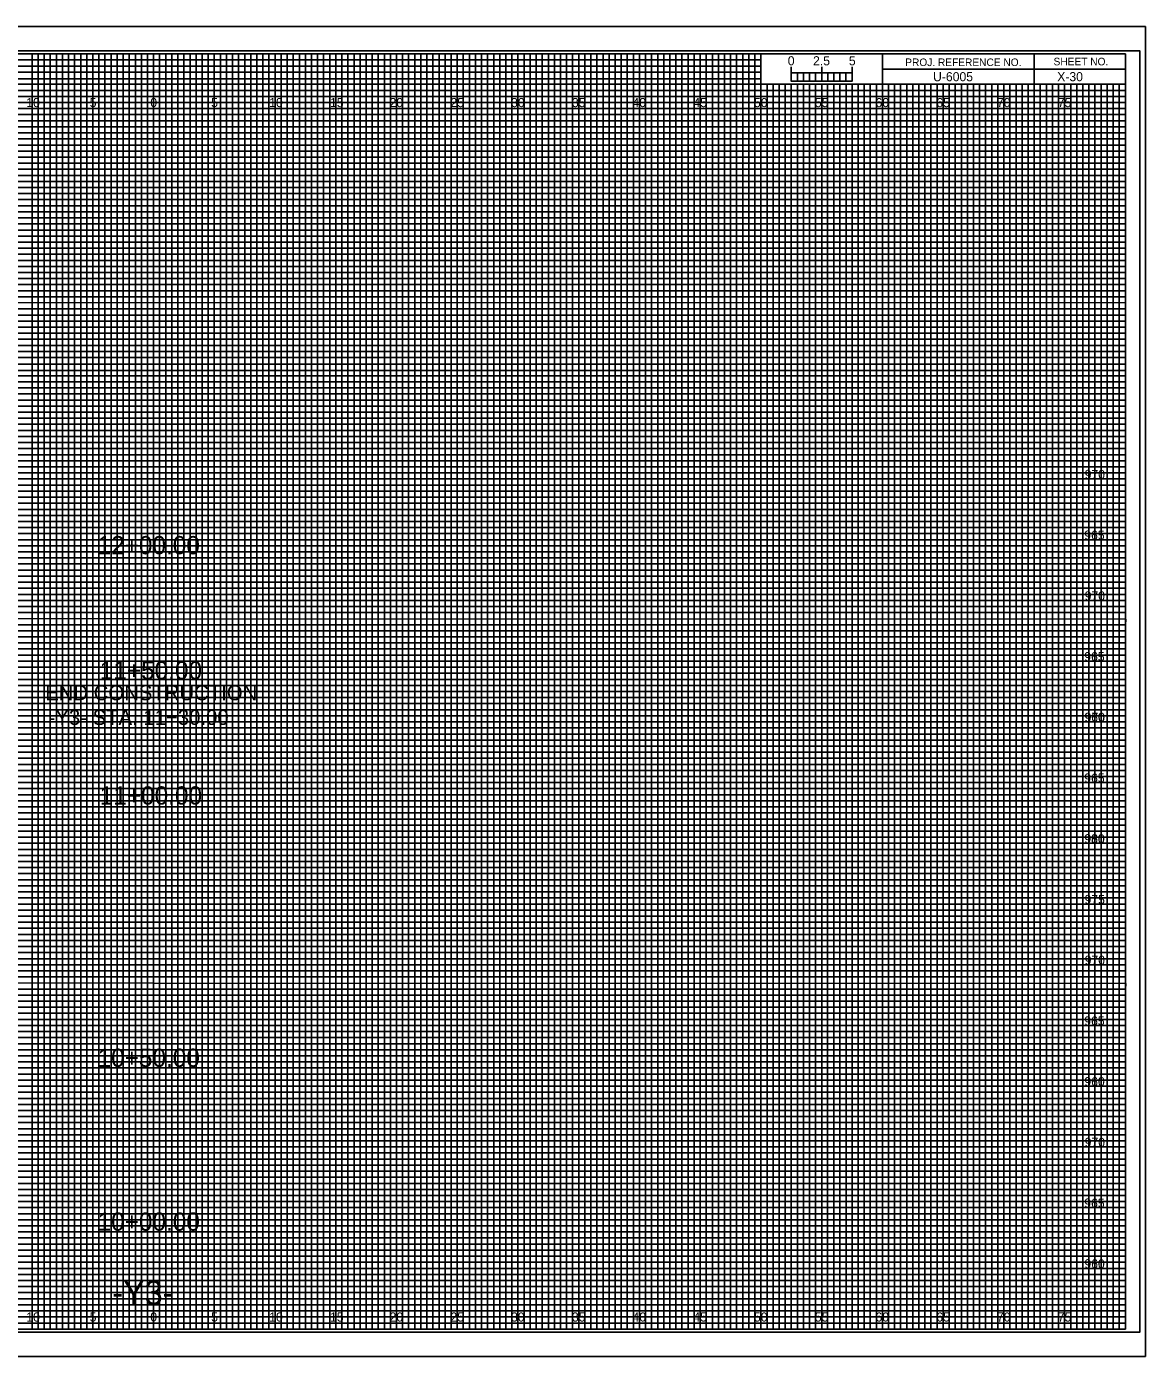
# Model space of a CAD drawing. Extents: x -7 to 162, y -2 to 107.
# Drawn here: x 69.5 to 161.7, y -2.3 to 107.3 of the extents above; entities that cross this region are included whole.
import ezdxf

# ---------------------------------------------------------------- set-up
doc = ezdxf.new("R2010")
doc.units = 0
for name, color, linetype in [('Prop XS Alignment Label', 7, 'Continuous'), ('Prop XS Bar Scale Labels', 7, 'Continuous'), ('Prop XS Elevation Labels', 7, 'Continuous'), ('Prop XS Label Text', 7, 'Continuous'), ('Prop XS Offset Labels', 7, 'Continuous'), ('Prop XS Project Number', 7, 'Continuous'), ('Prop XS Sheet Number', 7, 'Continuous'), ('Prop XS Station Labels', 7, 'Continuous'), ('Sheet Cross Section CELL', 7, 'Continuous'), ('Sheet Cross Section Grid Major CELL', 7, 'Continuous'), ('Sheet Cross Section Grid Middle CELL', 7, 'Continuous'), ('Sheet Cross Section Grid Minor 1 CELL', 7, 'Continuous'), ('Sheet Cross Section Grid Minor 2 CELL', 7, 'Continuous'), ('Sheet Cross Section Scale CELL', 7, 'Continuous'), ('Sheet Cutting Line CELL', 7, 'Continuous'), ('Sheet DOT Grid CELL', 7, 'Continuous'), ('Sheet Plot Border Inside CELL', 7, 'Continuous'), ('Sheet Plot Border Outside CELL', 7, 'Continuous')]:
    doc.layers.add(name, color=color, linetype=linetype)

msp = doc.modelspace()

# ---------------------------------------------------------------- linework, layer by layer
at = {"layer": 'Sheet Cross Section CELL'}
for p, q in [((152.5, 105), (152.5, 102.5)), ((152.5, 102.5), (152.5, 105)), ((160, 103.75), (140, 103.75)), ((140, 103.75), (140, 102.5)), ((140, 102.5), (160, 102.5))]:
    msp.add_line(p, q, dxfattribs=at)
for points in [[(160, 105), (0, 105), (0, 0), (160, 0)], [(140, 105), (130, 105), (130, 102.52), (140, 102.52)], [(160, 105), (140, 105), (140, 102.5), (160, 102.5)]]:
    msp.add_lwpolyline(points, close=True, dxfattribs=at)
at = {"layer": 'Sheet Cross Section Grid Major CELL'}
for p, q in [((75, 105), (70, 105)), ((70, 105), (70, 0)), ((75, 0), (75, 105)), ((85, 105), (80, 105)), ((80, 105), (80, 0)), ((85, 0), (85, 105)), ((95, 105), (90, 105)), ((90, 105), (90, 0)), ((95, 0), (95, 105)), ((105, 105), (100, 105)), ((100, 105), (100, 0)), ((105, 0), (105, 105)), ((115, 105), (110, 105)), ((110, 105), (110, 0)), ((115, 0), (115, 105)), ((125, 105), (120, 105)), ((120, 105), (120, 0)), ((125, 0), (125, 105)), ((130, 105), (130, 0)), ((135, 0), (135, 102.5)), ((145, 102.5), (140, 102.5)), ((140, 102.5), (140, 0)), ((145, 0), (145, 102.5)), ((155, 102.5), (150, 102.5)), ((150, 102.5), (150, 0)), ((155, 0), (155, 102.5)), ((70, 0), (65, 0)), ((80, 0), (75, 0)), ((90, 0), (85, 0)), ((100, 0), (95, 0)), ((110, 0), (105, 0)), ((120, 0), (115, 0)), ((130, 0), (125, 0)), ((140, 0), (135, 0)), ((150, 0), (145, 0)), ((160, 0), (155, 0)), ((160, 0), (160, 0))]:
    msp.add_line(p, q, dxfattribs=at)
for points in [[(0, 100), (160, 100), (160, 95), (0, 95)], [(0, 90), (160, 90), (160, 85), (0, 85)], [(0, 80), (160, 80), (160, 75), (0, 75)], [(0, 70), (160, 70), (160, 65), (0, 65)], [(0, 60), (160, 60), (160, 55), (0, 55)], [(0, 50), (160, 50), (160, 45), (0, 45)], [(0, 40), (160, 40), (160, 35), (0, 35)], [(0, 30), (160, 30), (160, 25), (0, 25)], [(0, 20), (160, 20), (160, 15), (0, 15)], [(0, 10), (160, 10), (160, 5), (0, 5)]]:
    msp.add_lwpolyline(points, dxfattribs=at)
at = {"layer": 'Sheet Cross Section Grid Middle CELL'}
for points in [[(67.5, 105), (72.5, 105), (72.5, 0), (77.5, 0), (77.5, 105), (82.5, 105), (82.5, 0), (87.5, 0), (87.5, 105), (92.5, 105), (92.5, 0), (97.5, 0), (97.5, 105), (102.5, 105), (102.5, 0), (107.5, 0), (107.5, 105), (112.5, 105), (112.5, 0), (117.5, 0), (117.5, 105), (122.5, 105), (122.5, 0), (127.5, 0), (127.5, 105), (129.97, 105), (130, 105), (130, 102.5), (132.5, 102.5), (132.5, 0), (137.5, 0), (137.5, 102.5), (142.5, 102.5), (142.5, 0), (147.5, 0), (147.5, 102.5), (152.5, 102.5), (152.5, 0), (157.5, 0), (157.5, 102.5)], [(0, 102.5), (137.5, 102.5)], [(0, 92.5), (160, 92.5), (160, 97.5), (0, 97.5)], [(0, 82.5), (160, 82.5), (160, 87.5), (0, 87.5)], [(0, 72.5), (160, 72.5), (160, 77.5), (0, 77.5)], [(0, 62.5), (160, 62.5), (160, 67.5), (0, 67.5)], [(0, 52.5), (160, 52.5), (160, 57.5), (0, 57.5)], [(0, 42.5), (160, 42.5), (160, 47.5), (0, 47.5)], [(0, 32.5), (160, 32.5), (160, 37.5), (0, 37.5)], [(0, 22.5), (160, 22.5), (160, 27.5), (0, 27.5)], [(0, 12.5), (160, 12.5), (160, 17.5), (0, 17.5)], [(0, 2.5), (160, 2.5), (160, 7.5), (0, 7.5)]]:
    msp.add_lwpolyline(points, dxfattribs=at)
at = {"layer": 'Sheet Cross Section Grid Minor 1 CELL'}
for p, q in [((0, 104.5), (130, 104.5)), ((130, 104.5), (130, 103.99)), ((130, 103.99), (0, 103.99)), ((0, 103.5), (130, 103.5)), ((130, 102.95), (0, 102.95)), ((130, 103.5), (130, 102.95)), ((0, 102), (160, 102))]:
    msp.add_line(p, q, dxfattribs=at)
for points in [[(0, 101.5), (135, 101.5), (160, 101.5), (160, 101), (0, 101)], [(0, 100.5), (160, 100.5), (160, 99.5), (0, 99.5)], [(0, 99), (160, 99), (160, 98.5), (0, 98.49)], [(0, 98), (160, 98), (160, 97), (0, 97)], [(0, 96.5), (160, 96.5), (160, 96), (0, 96)], [(0, 95.5), (160, 95.5), (160, 94.5), (0, 94.5)], [(0, 94), (160, 94), (160, 93.5), (0, 93.5)], [(0, 93), (160, 93), (160, 92), (0, 92)], [(0, 91.5), (160, 91.5), (160, 91), (0, 91)], [(0, 90.5), (160, 90.5), (160, 89.5), (0, 89.5)], [(0, 89), (160, 89), (160, 88.5), (0, 88.5)], [(0, 88), (160, 88), (160, 86.98), (160, 86.5), (160, 86), (0, 86)], [(0, 87), (160, 87), (160, 86.5), (0, 86.5)], [(0, 85.5), (160, 85.5), (160, 84.5), (0, 84.52)], [(0, 84.52), (160, 84.5), (160, 84), (0, 84)], [(0, 83.5), (160, 83.5), (160, 83), (0, 83)], [(0, 82), (160, 82), (160, 81.5), (0, 81.5)], [(0, 81), (160, 81), (160, 80.5), (0, 80.5)], [(-0.04, 79.45), (160, 79.45), (160, 78.94), (-0.04, 78.94)], [(0, 78.5), (160, 78.5), (160, 78), (0, 78)], [(0, 77), (160, 77), (160, 76.5), (0, 76.5)], [(0, 76), (160, 76), (160, 75.5), (0, 75.5)], [(0, 74.5), (160, 74.5), (160, 74), (0, 74)], [(0, 73.5), (160, 73.5), (160, 73), (0, 73)], [(0, 72), (160, 72), (160, 71.5), (0, 71.5)], [(0, 71), (160, 71), (160, 70.5), (0, 70.5)], [(0, 69.5), (160, 69.5), (160, 68.99), (0, 69)], [(0, 68.5), (160, 68.5), (160, 68), (0, 68)], [(0, 67), (160, 67), (160, 66.5), (0, 66.5)], [(0, 66), (160, 66), (160, 65.5), (0, 65.5)], [(0, 64.5), (160, 64.5), (160, 64), (0, 64)], [(0, 63.5), (160, 63.5), (160, 63), (0, 63)], [(0, 62), (160, 62), (160, 61.5), (0, 61.5)], [(0, 61), (160, 61), (160, 60.5), (0, 60.5)], [(0, 59.5), (160, 59.5), (160, 59), (0, 59)], [(0, 58.5), (160.03, 58.45), (160, 58), (0, 58)], [(0, 57), (160, 57), (160, 56.5), (0, 56.5)], [(0, 56), (160, 56), (160, 55.5), (0, 55.5)], [(0, 54.5), (160, 54.5), (160, 54), (0, 54)], [(0, 53.5), (160, 53.5), (160, 53), (0, 53)], [(0, 52), (160, 52), (160, 51.5), (0, 51.5)], [(0, 51), (160, 51), (160, 50.5), (0, 50.5)], [(0, 49.5), (160, 49.5), (160, 49), (0, 49)], [(0, 48.5), (160, 48.5), (160, 48), (0, 48)], [(0, 47), (160, 47), (160, 46.5), (0, 46.5)], [(0, 46), (160, 46), (160, 45.5), (0, 45.5)], [(0, 44.5), (160, 44.5), (160, 44), (0, 44)], [(0, 43.5), (160, 43.5), (160, 43), (0, 43)], [(0, 42), (160, 42), (160, 41.5), (0, 41.5)], [(0, 41), (160, 41), (160, 40.5), (0, 40.5)], [(0, 39.5), (160, 39.5), (160, 38.99), (0, 39)], [(0, 38.5), (160, 38.5), (160, 38), (0, 38)], [(0, 37), (160, 37), (160, 36.5), (0, 36.5)], [(0, 36), (160, 36), (160, 35.5), (0, 35.5)], [(0, 34.5), (160, 34.5), (160, 34), (0, 34)], [(0, 33.5), (160, 33.5), (160, 33), (0, 33)], [(0, 32), (160, 32), (160, 31.5), (0, 31.5)], [(0, 31), (160, 31), (160, 30.5), (0, 30.5)], [(0, 29.5), (160, 29.5), (160, 29), (0, 29)], [(0, 28.5), (160.03, 28.46), (160, 28), (0, 28)], [(0, 27), (160, 27), (160, 26.5), (0, 26.5)], [(0, 26), (160, 26), (160, 25.5), (0, 25.5)], [(0, 24.5), (160, 24.5), (160, 24), (0, 24)], [(0, 23.5), (160, 23.5), (160, 23), (0, 23)], [(0, 22), (160, 22), (160, 21.5), (0, 21.5)], [(0, 21), (160, 21), (160, 20.5), (0, 20.5)], [(0, 19.5), (160, 19.5), (160, 19), (0, 19)], [(0, 18.5), (160, 18.5), (160, 18), (0, 18)], [(0, 17), (160, 17), (160, 16.5), (0, 16.5)], [(0, 16), (160, 16), (160, 15.5), (0, 15.5)], [(0, 14.5), (160, 14.5), (160, 14), (0, 14)], [(0, 13.5), (160, 13.5), (160, 13), (0, 13)], [(0, 12), (160, 12), (160, 11.5), (0, 11.5)], [(0, 11), (160, 11), (160, 10.5), (0, 10.5)], [(0, 9.5), (160, 9.5), (160, 9), (0, 9)], [(0, 8.5), (160, 8.5), (160, 8), (0, 8)], [(0, 7), (160, 7), (160, 6.5), (0, 6.5)], [(0, 6), (160, 6), (160, 5.5), (0, 5.5)], [(0, 4.5), (160, 4.5), (160, 4), (0, 4)], [(0, 3.5), (160, 3.5), (160, 3), (0, 3)], [(0, 2), (160, 2), (160, 1.5), (0, 1.5)], [(0, 1), (160, 1), (160, 0.5), (0, 0.5)]]:
    msp.add_lwpolyline(points, dxfattribs=at)
at = {"layer": 'Sheet Cross Section Grid Minor 2 CELL'}
for p, q in [((133.5, 102.5), (133, 102.5)), ((133, 102.5), (133, 0)), ((133.5, 0), (133.5, 102.5)), ((134.5, 102.5), (134, 102.5)), ((134, 102.5), (134, 0)), ((134.5, 0), (134.5, 102.5)), ((133, 0), (132.5, 0)), ((134, 0), (133.5, 0))]:
    msp.add_line(p, q, dxfattribs=at)
for points in [[(70, 0), (70.5, 0), (70.5, 105), (71, 105), (71, 0)], [(71, 0), (71.5, 0), (71.5, 105), (72, 105), (72, 0)], [(72.5, 0), (73, 0), (73, 105), (73.5, 105), (73.5, 0)], [(73.5, 0), (74, 0), (74, 105), (74.5, 105), (74.5, 0)], [(75, 0), (75.5, 0), (75.5, 105), (76, 105), (76, 0)], [(76, 0), (76.5, 0), (76.5, 105), (77, 105), (77, 0)], [(77.5, 0), (78, 0), (78, 105), (78.5, 105), (78.5, 0)], [(78.5, 0), (79, 0), (79, 105), (79.5, 105), (79.5, 0)], [(80, 0), (80.5, 0), (80.5, 105), (81, 105), (81, 0)], [(81, 0), (81.5, 0), (81.5, 105), (82, 105), (82, 0)], [(82.5, 0), (83, 0), (83, 105), (83.5, 105), (83.5, 0)], [(83.5, 0), (84, 0), (84, 105), (84.5, 105), (84.5, 0)], [(85, 0), (85.5, 0), (85.5, 105), (86, 105), (86, 0)], [(86, 0), (86.5, 0), (86.5, 105), (87, 105), (87, 0)], [(87.5, 0), (88, 0), (88, 105), (88.5, 105), (88.5, 0)], [(88.5, 0), (89, 0), (89, 105), (89.5, 105), (89.5, 0)], [(90, 0), (90.5, 0), (90.5, 105), (91, 105), (91, 0)], [(91, 0), (91.5, 0), (91.5, 105), (92, 105), (92, 0)], [(92.5, 0), (93, 0), (93, 105), (93.5, 105), (93.5, 0)], [(93.5, 0), (94, 0), (94, 105), (94.5, 105), (94.5, 0)], [(95, 0), (95.5, 0), (95.5, 105), (96, 105), (96, 0)], [(96, 0), (96.5, 0), (96.5, 105), (97, 105), (97, 0)], [(97.5, 0), (98, 0), (98, 105), (98.5, 105), (98.5, 0)], [(98.5, 0), (99, 0), (99, 105), (99.5, 105), (99.5, 0)], [(100, 0), (100.5, 0), (100.5, 105), (101, 105), (101, 0)], [(101, 0), (101.5, 0), (101.5, 105), (102, 105), (102, 0)], [(102.5, 0), (103, 0), (103, 105), (103.5, 105), (103.5, 0)], [(103.5, 0), (104, 0), (104, 105), (104.5, 105), (104.5, 0)], [(105, 0), (105.5, 0), (105.5, 105), (106, 105), (106, 0)], [(106, 0), (106.5, 0), (106.5, 105), (107, 105), (107, 0)], [(107.5, 0), (108, 0), (108, 105), (108.5, 105), (108.5, 0)], [(108.5, 0), (109, 0), (109, 105), (109.5, 105), (109.5, 0)], [(110, 0), (110.5, 0), (110.5, 105), (111, 105), (111, 0)], [(111, 0), (111.5, 0), (111.5, 105), (112, 105), (112, 0)], [(112.5, 0), (113, 0), (113, 105), (113.5, 105), (113.5, 0)], [(113.5, 0), (114, 0), (114, 105), (114.5, 105), (114.5, 0)], [(115, 0), (115.5, 0), (115.5, 105), (116, 105), (116, 0)], [(116, 0), (116.5, 0), (116.5, 105), (117, 105), (117, 0)], [(117.5, 0), (118, 0), (118, 105), (118.5, 105), (118.5, 0)], [(118.5, 0), (119, 0), (119, 105), (119.5, 105), (119.5, 0)], [(120, 0), (120.5, 0), (120.5, 105), (121, 105), (121, 0)], [(121, 0), (121.5, 0), (121.5, 105), (122, 105), (122, 0)], [(122.5, 0), (123, 0), (123, 105), (123.5, 105), (123.5, 0)], [(123.5, 0), (124, 0), (124, 105), (124.5, 105), (124.5, 0)], [(125, 0), (125.5, 0), (125.5, 105), (126, 105), (126, 0)], [(126, 0), (126.5, 0), (126.5, 105), (127, 105), (127, 0)], [(127.5, 0), (128, 0), (128, 105), (128.5, 105), (128.5, 0)], [(128.5, 0), (129, 0), (129, 105), (129.5, 105), (129.5, 0)], [(130, 0), (130.5, 0), (130.5, 102.5), (131.01, 102.5), (131.01, 0)], [(131, 0), (131.5, 0), (131.5, 102.5), (132, 102.5), (132, 0)], [(135, 0), (135.49, 0), (135.49, 102.5), (136, 102.5), (136, 0)], [(136, 0), (136.5, 0), (136.5, 102.5), (137.03, 102.5), (137.03, 0)], [(137.5, 0), (138, 0), (138, 102.5), (138.5, 102.5), (138.5, 0)], [(138.5, 0), (139, 0), (139, 102.5), (139.5, 102.5), (139.5, 0)], [(140, 0), (140.5, 0), (140.5, 102.5), (141, 102.5), (141, 0)], [(141, 0), (141.5, 0), (141.5, 102.5), (142, 102.5), (142, 0)], [(142.5, 0), (143, 0), (143, 102.5), (143.5, 102.5), (143.5, 0)], [(143.5, 0), (144, 0), (144, 102.5), (144.5, 102.5), (144.5, 0)], [(145, 0), (145.5, 0), (145.5, 102.5), (146, 102.5), (146, 0)], [(146, 0), (146.5, 0), (146.5, 102.5), (147, 102.5), (147, 0)], [(147.5, 0), (148, 0), (148, 102.5), (148.5, 102.5), (148.5, 0)], [(148.5, 0), (149, 0), (149, 102.5), (149.5, 102.5), (149.5, 0)], [(150, 0), (150.5, 0), (150.5, 102.5), (151, 102.5), (151, 0)], [(151, 0), (151.5, 0), (151.5, 102.5), (152, 102.5), (152, 0)], [(152.5, 0), (153, 0), (153, 102.5), (153.5, 102.5), (153.5, 0)], [(153.5, 0), (154, 0), (154, 102.5), (154.5, 102.5), (154.5, 0)], [(155, 0), (155.5, 0), (155.5, 102.5), (156, 102.5), (156, 0)], [(156, 0), (156.5, 0), (156.5, 102.5), (157, 102.5), (157, 0)], [(157.5, 0), (158, 0), (158, 102.5), (158.5, 102.5), (158.5, 0)], [(158.5, 0), (159, 0), (159, 102.5), (159.5, 102.5), (159.5, 0)]]:
    msp.add_lwpolyline(points, dxfattribs=at)
at = {"layer": 'Sheet Cross Section Scale CELL'}
for p, q in [((132.5, 102.75), (132.5, 103.95)), ((132.5, 103.45), (132.5, 103.95)), ((135, 102.75), (135, 103.95)), ((137.5, 102.75), (137.5, 103.95)), ((137.5, 103.45), (137.5, 103.95))]:
    msp.add_line(p, q, dxfattribs=at)
for points in [[(137.5, 103.45), (132.5, 103.45), (132.5, 102.75), (137.5, 102.75)], [(132.5, 103.45), (133, 103.45), (133, 102.75), (132.5, 102.75)], [(133.5, 103.45), (134, 103.45), (134, 102.75), (133.5, 102.75)], [(134.5, 103.45), (135, 103.45), (135, 102.75), (134.5, 102.75)], [(135.5, 103.45), (136, 103.45), (136, 102.75), (135.5, 102.75)], [(136.5, 103.45), (137, 103.45), (137, 102.75), (136.5, 102.75)]]:
    msp.add_lwpolyline(points, close=True, dxfattribs=at)
at = {"layer": 'Sheet Cutting Line CELL'}
for p, q in [((161.65, 107.25), (-6.7, 107.25)), ((-6.7, -2.25), (161.65, -2.25))]:
    msp.add_line(p, q, dxfattribs=at)
at = {"layer": 'Sheet DOT Grid CELL'}
for p, q in [((70, 0), (70, 105)), ((75, 0), (75, 105)), ((80, 0), (80, 105)), ((85, 0), (85, 105)), ((90, 0), (90, 105)), ((95, 0), (95, 105)), ((100, 0), (100, 105)), ((105, 0), (105, 105)), ((110, 0), (110, 105)), ((115, 0), (115, 105)), ((120, 0), (120, 105)), ((125, 0), (125, 105)), ((130, 0), (130, 102.34)), ((135, 0), (135, 102.34)), ((140, 0), (140, 102.34)), ((145, 0), (145, 102.34)), ((150, 0), (150, 102.34)), ((155, 0), (155, 102.34)), ((0, 100), (160, 100)), ((0, 95), (160, 95)), ((0, 90), (160, 90)), ((0, 85), (160, 85)), ((0, 80), (160, 80)), ((0, 75), (160, 75)), ((0, 70), (160, 70)), ((0, 65), (160, 65)), ((0, 60), (160, 60)), ((0, 55), (160, 55)), ((0, 50), (160, 50)), ((0, 45), (160, 45)), ((0, 40), (160, 40)), ((0, 35), (160, 35)), ((0, 30), (160, 30)), ((0, 25), (160, 25)), ((0, 20), (160, 20)), ((0, 15), (160, 15)), ((0, 10), (160, 10)), ((0, 5), (160, 5))]:
    msp.add_line(p, q, dxfattribs=at)
at = {"layer": 'Sheet Plot Border Inside CELL'}
msp.add_lwpolyline([(-5.4, -0.25), (161.2, -0.25), (161.2, 105.25), (-5.4, 105.25)], close=True, dxfattribs=at)
at = {"layer": 'Sheet Plot Border Outside CELL'}
msp.add_lwpolyline([(-6.7, -2.25), (161.65, -2.25), (161.65, 107.25), (-6.7, 107.25)], close=True, dxfattribs=at)

# ---------------------------------------------------------------- texts
at = {"layer": 'Prop XS Alignment Label'}
msp.add_text('-Y3-', height=2, dxfattribs=at).set_placement((76.59, 2))
at = {"layer": 'Prop XS Bar Scale Labels'}
for s, p in [('2.5', (134.29, 104.06)), ('5', (137.24, 104.06))]:
    msp.add_text(s, height=0.75, dxfattribs=at).set_placement(p)
at = {"layer": 'Prop XS Elevation Labels'}
for s, p in [('970', (156.65, 70)), ('965', (156.62, 65)), ('970', (156.65, 60)), ('965', (156.62, 55)), ('960', (156.63, 50)), ('970', (156.65, 50)), ('965', (156.62, 45)), ('980', (156.62, 40)), ('960', (156.63, 40)), ('975', (156.64, 35)), ('970', (156.65, 30)), ('965', (156.62, 25)), ('960', (156.63, 20)), ('970', (156.65, 15)), ('965', (156.62, 10)), ('960', (156.63, 5))]:
    msp.add_text(s, height=0.75, dxfattribs=at).set_placement(p)
at = {"layer": 'Prop XS Label Text'}
for s, p in [('END CONSTRUCTION', (71.08, 51.78)), ('-Y3- STA. 11+30.00', (71.36, 49.75))]:
    msp.add_text(s, height=1.25, dxfattribs=at).set_placement(p)
at = {"layer": 'Prop XS Offset Labels'}
for s, p in [('10', (69.52, 100.62)), ('5', (74.74, 100.62)), ('0', (79.73, 100.62)), ('0', (79.73, 100.62)), ('5', (84.74, 100.62)), ('10', (89.52, 100.62)), ('15', (94.53, 100.62)), ('20', (99.43, 100.62)), ('25', (104.44, 100.62)), ('30', (109.43, 100.62)), ('35', (114.44, 100.62)), ('40', (119.43, 100.62)), ('45', (124.44, 100.62)), ('50', (129.43, 100.62)), ('55', (134.44, 100.62)), ('60', (139.43, 100.62)), ('65', (144.44, 100.62)), ('70', (149.43, 100.62)), ('75', (154.44, 100.62)), ('10', (69.52, 0.62)), ('5', (74.74, 0.62)), ('0', (79.73, 0.62)), ('0', (79.73, 0.62)), ('5', (84.74, 0.62)), ('10', (89.52, 0.62)), ('15', (94.53, 0.62)), ('20', (99.43, 0.62)), ('25', (104.44, 0.62)), ('30', (109.43, 0.62)), ('35', (114.44, 0.62)), ('40', (119.43, 0.62)), ('45', (124.44, 0.62)), ('50', (129.43, 0.62)), ('55', (134.44, 0.62)), ('60', (139.43, 0.62)), ('65', (144.44, 0.62)), ('70', (149.43, 0.62)), ('75', (154.44, 0.62))]:
    msp.add_text(s, height=0.75, dxfattribs=at).set_placement(p)
at = {"layer": 'Prop XS Project Number'}
msp.add_text('U-6005', height=0.75, dxfattribs=at).set_placement((144.17, 102.75))
at = {"layer": 'Prop XS Sheet Number'}
msp.add_text('X-30', height=0.75, dxfattribs=at).set_placement((154.39, 102.75))
at = {"layer": 'Prop XS Station Labels'}
for s, p in [('12+00.00', (75.39, 63.8)), ('11+50.00', (75.57, 53.49)), ('11+00.00', (75.57, 43.19)), ('10+50.00', (75.39, 21.59)), ('10+00.00', (75.39, 8.1))]:
    msp.add_text(s, height=1.5, dxfattribs=at).set_placement(p)
at = {"layer": 'Sheet Cross Section CELL'}
for s, p in [('PROJ. REFERENCE NO.', (141.88, 104)), ('SHEET NO.', (154.09, 104.06))]:
    msp.add_text(s, height=0.625, dxfattribs=at).set_placement(p)
at = {"layer": 'Sheet Cross Section Scale CELL'}
msp.add_text('0', height=0.75, dxfattribs=at).set_placement((132.21, 104.06))

doc.saveas('drawing.dxf')
